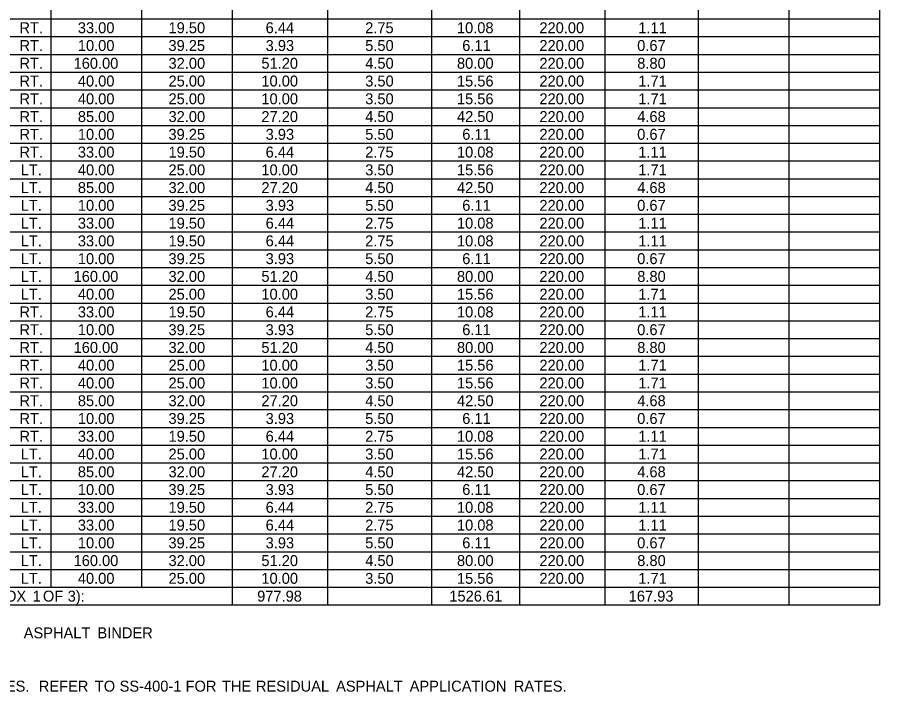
# Model space of a CAD drawing. Extents: x 544478 to 1930787, y -1948294 to 596640.
# Drawn here: x 550607 to 551080, y -1946928.5 to -1946558.2 of the extents above; entities that cross this region are included whole.
import ezdxf

# ---------------------------------------------------------------- set-up
doc = ezdxf.new("R2010")
doc.units = 0
doc.layers.add('Default', color=7, linetype='Continuous')

msp = doc.modelspace()

# ---------------------------------------------------------------- linework, layer by layer
at = {"layer": 'Default'}
for p, q in [((550625.62, -1946871.09), (550625.62, -1946192.49)), ((550675.35, -1946871.09), (550675.35, -1946192.49)), ((550777.23, -1946880.84), (550777.23, -1946192.49)), ((551079.97, -1946880.84), (551079.97, -1946192.49)), ((550725.07, -1946880.84), (550725.07, -1946217.84)), ((550834.27, -1946880.84), (550834.27, -1946217.84)), ((550882.53, -1946880.84), (550882.53, -1946217.84)), ((550929.33, -1946880.84), (550929.33, -1946217.84)), ((550980.52, -1946880.84), (550980.52, -1946217.84)), ((551030.25, -1946880.84), (551030.25, -1946217.84)), ((550675.35, -1946871.09), (550675.35, -1946237.34)), ((550834.27, -1946880.84), (550834.27, -1946237.34)), ((550625.62, -1946871.09), (550625.62, -1946247.09)), ((550725.07, -1946880.84), (550725.07, -1946247.09)), ((550882.53, -1946880.84), (550882.53, -1946247.09)), ((550257.56, -1946559.09), (551079.97, -1946559.09)), ((550929.33, -1946559.09), (551030.25, -1946559.09)), ((550503.26, -1946568.84), (551079.97, -1946568.84)), ((550503.26, -1946578.59), (551079.97, -1946578.59)), ((550503.26, -1946588.34), (551079.97, -1946588.34)), ((550503.26, -1946598.09), (551079.97, -1946598.09)), ((550503.26, -1946607.84), (551079.97, -1946607.84)), ((550503.26, -1946617.59), (551079.97, -1946617.59)), ((550503.26, -1946627.34), (551079.97, -1946627.34)), ((550503.26, -1946637.09), (551079.97, -1946637.09)), ((550503.26, -1946646.84), (551079.97, -1946646.84)), ((550503.26, -1946656.59), (551079.97, -1946656.59)), ((550503.26, -1946666.34), (551079.97, -1946666.34)), ((550503.26, -1946676.09), (550777.23, -1946676.09)), ((550725.07, -1946676.09), (550777.23, -1946676.09)), ((550777.23, -1946676.09), (551079.97, -1946676.09)), ((550503.26, -1946685.84), (551079.97, -1946685.84)), ((550503.26, -1946695.59), (550777.23, -1946695.59)), ((550725.07, -1946695.59), (550777.23, -1946695.59)), ((550777.23, -1946695.59), (551079.97, -1946695.59)), ((550503.26, -1946705.34), (550777.23, -1946705.34)), ((550725.07, -1946705.34), (550777.23, -1946705.34)), ((550777.23, -1946705.34), (551079.97, -1946705.34)), ((550257.56, -1946715.09), (551079.97, -1946715.09)), ((550503.26, -1946724.84), (551079.97, -1946724.84)), ((550503.26, -1946734.59), (551079.97, -1946734.59)), ((550503.26, -1946744.34), (551079.97, -1946744.34)), ((550503.26, -1946754.09), (551079.97, -1946754.09)), ((550503.26, -1946763.84), (551079.97, -1946763.84)), ((550503.26, -1946773.59), (551079.97, -1946773.59)), ((550503.26, -1946783.34), (551079.97, -1946783.34)), ((550503.26, -1946793.09), (551079.97, -1946793.09)), ((550503.26, -1946802.84), (551079.97, -1946802.84)), ((550503.26, -1946812.59), (551079.97, -1946812.59)), ((550503.26, -1946822.34), (551079.97, -1946822.34)), ((550503.26, -1946832.09), (550777.23, -1946832.09)), ((550725.07, -1946832.09), (550777.23, -1946832.09)), ((550777.23, -1946832.09), (551079.97, -1946832.09)), ((550503.26, -1946841.84), (551079.97, -1946841.84)), ((550503.26, -1946851.59), (550777.23, -1946851.59)), ((550725.07, -1946851.59), (550777.23, -1946851.59)), ((550777.23, -1946851.59), (551079.97, -1946851.59)), ((550503.26, -1946861.34), (550777.23, -1946861.34)), ((550725.07, -1946861.34), (550777.23, -1946861.34)), ((550777.23, -1946861.34), (551079.97, -1946861.34)), ((550257.56, -1946871.09), (551079.97, -1946871.09)), ((550929.33, -1946880.84), (550929.33, -1946871.09)), ((550503.26, -1946880.84), (551079.97, -1946880.84))]:
    msp.add_line(p, q, dxfattribs=at)

# ---------------------------------------------------------------- texts
for s, p in [(' RT.', (550605.95, -1946566.97)), ('33.00', (550640.2, -1946566.97)), ('19.50', (550689.93, -1946566.97)), ('6.44', (550743.2, -1946566.97)), ('2.75', (550797.77, -1946566.97)), ('10.08', (550848.1, -1946566.97)), ('220.00', (550893.32, -1946566.97)), ('1.11', (550947.55, -1946566.97)), (' RT.', (550605.95, -1946576.72)), ('10.00', (550640.2, -1946576.72)), ('39.25', (550689.89, -1946576.72)), ('3.93', (550743.19, -1946576.72)), ('5.50', (550797.8, -1946576.72)), ('6.11', (550851.02, -1946576.72)), ('220.00', (550893.32, -1946576.72)), ('0.67', (550946.96, -1946576.72)), (' RT.', (550605.95, -1946586.47)), ('160.00', (550637.87, -1946586.47)), ('32.00', (550689.93, -1946586.47)), ('51.20', (550740.87, -1946586.47)), ('4.50', (550797.8, -1946586.47)), ('80.00', (550848.12, -1946586.47)), ('220.00', (550893.32, -1946586.47)), ('8.80', (550946.98, -1946586.47)), (' RT.', (550605.95, -1946596.22)), ('40.00', (550640.2, -1946596.22)), ('25.00', (550689.93, -1946596.22)), ('10.00', (550740.87, -1946596.22)), ('3.50', (550797.8, -1946596.22)), ('15.56', (550848.11, -1946596.22)), ('220.00', (550893.32, -1946596.22)), ('1.71', (550947.55, -1946596.22)), (' RT.', (550605.95, -1946605.97)), ('40.00', (550640.2, -1946605.97)), ('25.00', (550689.93, -1946605.97)), ('10.00', (550740.87, -1946605.97)), ('3.50', (550797.8, -1946605.97)), ('15.56', (550848.11, -1946605.97)), ('220.00', (550893.32, -1946605.97)), ('1.71', (550947.55, -1946605.97)), (' RT.', (550605.95, -1946615.72)), ('85.00', (550640.2, -1946615.72)), ('32.00', (550689.93, -1946615.72)), ('27.20', (550740.87, -1946615.72)), ('4.50', (550797.8, -1946615.72)), ('42.50', (550848.12, -1946615.72)), ('220.00', (550893.32, -1946615.72)), ('4.68', (550946.96, -1946615.72)), (' RT.', (550605.95, -1946625.47)), ('10.00', (550640.2, -1946625.47)), ('39.25', (550689.89, -1946625.47)), ('3.93', (550743.19, -1946625.47)), ('5.50', (550797.8, -1946625.47)), ('6.11', (550851.02, -1946625.47)), ('220.00', (550893.32, -1946625.47)), ('0.67', (550946.96, -1946625.47)), (' RT.', (550605.95, -1946635.22)), ('33.00', (550640.2, -1946635.22)), ('19.50', (550689.93, -1946635.22)), ('6.44', (550743.2, -1946635.22)), ('2.75', (550797.77, -1946635.22)), ('10.08', (550848.1, -1946635.22)), ('220.00', (550893.32, -1946635.22)), ('1.11', (550947.55, -1946635.22)), (' LT.', (550606.65, -1946644.97)), ('40.00', (550640.2, -1946644.97)), ('25.00', (550689.93, -1946644.97)), ('10.00', (550740.87, -1946644.97)), ('3.50', (550797.8, -1946644.97)), ('15.56', (550848.11, -1946644.97)), ('220.00', (550893.32, -1946644.97)), ('1.71', (550947.55, -1946644.97)), (' LT.', (550606.65, -1946654.72)), ('85.00', (550640.2, -1946654.72)), ('32.00', (550689.93, -1946654.72)), ('27.20', (550740.87, -1946654.72)), ('4.50', (550797.8, -1946654.72)), ('42.50', (550848.12, -1946654.72)), ('220.00', (550893.32, -1946654.72)), ('4.68', (550946.96, -1946654.72)), (' LT.', (550606.65, -1946664.47)), ('10.00', (550640.2, -1946664.47)), ('39.25', (550689.89, -1946664.47)), ('3.93', (550743.19, -1946664.47)), ('5.50', (550797.8, -1946664.47)), ('6.11', (550851.02, -1946664.47)), ('220.00', (550893.32, -1946664.47)), ('0.67', (550946.96, -1946664.47)), (' LT.', (550606.65, -1946674.22)), ('33.00', (550640.2, -1946674.22)), ('19.50', (550689.93, -1946674.22)), ('6.44', (550743.2, -1946674.22)), ('2.75', (550797.77, -1946674.22)), ('10.08', (550848.1, -1946674.22)), ('220.00', (550893.32, -1946674.22)), ('1.11', (550947.55, -1946674.22)), (' LT.', (550606.65, -1946683.97)), ('33.00', (550640.2, -1946683.97)), ('19.50', (550689.93, -1946683.97)), ('6.44', (550743.2, -1946683.97)), ('2.75', (550797.77, -1946683.97)), ('10.08', (550848.1, -1946683.97)), ('220.00', (550893.32, -1946683.97)), ('1.11', (550947.55, -1946683.97)), (' LT.', (550606.65, -1946693.72)), ('10.00', (550640.2, -1946693.72)), ('39.25', (550689.89, -1946693.72)), ('3.93', (550743.19, -1946693.72)), ('5.50', (550797.8, -1946693.72)), ('6.11', (550851.02, -1946693.72)), ('220.00', (550893.32, -1946693.72)), ('0.67', (550946.96, -1946693.72)), (' LT.', (550606.65, -1946703.47)), ('160.00', (550637.87, -1946703.47)), ('32.00', (550689.93, -1946703.47)), ('51.20', (550740.87, -1946703.47)), ('4.50', (550797.8, -1946703.47)), ('80.00', (550848.12, -1946703.47)), ('220.00', (550893.32, -1946703.47)), ('8.80', (550946.98, -1946703.47)), (' LT.', (550606.65, -1946713.22)), ('40.00', (550640.2, -1946713.22)), ('25.00', (550689.93, -1946713.22)), ('10.00', (550740.87, -1946713.22)), ('3.50', (550797.8, -1946713.22)), ('15.56', (550848.11, -1946713.22)), ('220.00', (550893.32, -1946713.22)), ('1.71', (550947.55, -1946713.22)), (' RT.', (550605.95, -1946722.97)), ('33.00', (550640.2, -1946722.97)), ('19.50', (550689.93, -1946722.97)), ('6.44', (550743.2, -1946722.97)), ('2.75', (550797.77, -1946722.97)), ('10.08', (550848.1, -1946722.97)), ('220.00', (550893.32, -1946722.97)), ('1.11', (550947.55, -1946722.97)), (' RT.', (550605.95, -1946732.72)), ('10.00', (550640.2, -1946732.72)), ('39.25', (550689.89, -1946732.72)), ('3.93', (550743.19, -1946732.72)), ('5.50', (550797.8, -1946732.72)), ('6.11', (550851.02, -1946732.72)), ('220.00', (550893.32, -1946732.72)), ('0.67', (550946.96, -1946732.72)), (' RT.', (550605.95, -1946742.47)), ('160.00', (550637.87, -1946742.47)), ('32.00', (550689.93, -1946742.47)), ('51.20', (550740.87, -1946742.47)), ('4.50', (550797.8, -1946742.47)), ('80.00', (550848.12, -1946742.47)), ('220.00', (550893.32, -1946742.47)), ('8.80', (550946.98, -1946742.47)), (' RT.', (550605.95, -1946752.22)), ('40.00', (550640.2, -1946752.22)), ('25.00', (550689.93, -1946752.22)), ('10.00', (550740.87, -1946752.22)), ('3.50', (550797.8, -1946752.22)), ('15.56', (550848.11, -1946752.22)), ('220.00', (550893.32, -1946752.22)), ('1.71', (550947.55, -1946752.22)), (' RT.', (550605.95, -1946761.97)), ('40.00', (550640.2, -1946761.97)), ('25.00', (550689.93, -1946761.97)), ('10.00', (550740.87, -1946761.97)), ('3.50', (550797.8, -1946761.97)), ('15.56', (550848.11, -1946761.97)), ('220.00', (550893.32, -1946761.97)), ('1.71', (550947.55, -1946761.97)), (' RT.', (550605.95, -1946771.72)), ('85.00', (550640.2, -1946771.72)), ('32.00', (550689.93, -1946771.72)), ('27.20', (550740.87, -1946771.72)), ('4.50', (550797.8, -1946771.72)), ('42.50', (550848.12, -1946771.72)), ('220.00', (550893.32, -1946771.72)), ('4.68', (550946.96, -1946771.72)), (' RT.', (550605.95, -1946781.47)), ('10.00', (550640.2, -1946781.47)), ('39.25', (550689.89, -1946781.47)), ('3.93', (550743.19, -1946781.47)), ('5.50', (550797.8, -1946781.47)), ('6.11', (550851.02, -1946781.47)), ('220.00', (550893.32, -1946781.47)), ('0.67', (550946.96, -1946781.47)), (' RT.', (550605.95, -1946791.22)), ('33.00', (550640.2, -1946791.22)), ('19.50', (550689.93, -1946791.22)), ('6.44', (550743.2, -1946791.22)), ('2.75', (550797.77, -1946791.22)), ('10.08', (550848.1, -1946791.22)), ('220.00', (550893.32, -1946791.22)), ('1.11', (550947.55, -1946791.22)), (' LT.', (550606.65, -1946800.97)), ('40.00', (550640.2, -1946800.97)), ('25.00', (550689.93, -1946800.97)), ('10.00', (550740.87, -1946800.97)), ('3.50', (550797.8, -1946800.97)), ('15.56', (550848.11, -1946800.97)), ('220.00', (550893.32, -1946800.97)), ('1.71', (550947.55, -1946800.97)), (' LT.', (550606.65, -1946810.72)), ('85.00', (550640.2, -1946810.72)), ('32.00', (550689.93, -1946810.72)), ('27.20', (550740.87, -1946810.72)), ('4.50', (550797.8, -1946810.72)), ('42.50', (550848.12, -1946810.72)), ('220.00', (550893.32, -1946810.72)), ('4.68', (550946.96, -1946810.72)), (' LT.', (550606.65, -1946820.47)), ('10.00', (550640.2, -1946820.47)), ('39.25', (550689.89, -1946820.47)), ('3.93', (550743.19, -1946820.47)), ('5.50', (550797.8, -1946820.47)), ('6.11', (550851.02, -1946820.47)), ('220.00', (550893.32, -1946820.47)), ('0.67', (550946.96, -1946820.47)), (' LT.', (550606.65, -1946830.22)), ('33.00', (550640.2, -1946830.22)), ('19.50', (550689.93, -1946830.22)), ('6.44', (550743.2, -1946830.22)), ('2.75', (550797.77, -1946830.22)), ('10.08', (550848.1, -1946830.22)), ('220.00', (550893.32, -1946830.22)), ('1.11', (550947.55, -1946830.22)), (' LT.', (550606.65, -1946839.97)), ('33.00', (550640.2, -1946839.97)), ('19.50', (550689.93, -1946839.97)), ('6.44', (550743.2, -1946839.97)), ('2.75', (550797.77, -1946839.97)), ('10.08', (550848.1, -1946839.97)), ('220.00', (550893.32, -1946839.97)), ('1.11', (550947.55, -1946839.97)), (' LT.', (550606.65, -1946849.72)), ('10.00', (550640.2, -1946849.72)), ('39.25', (550689.89, -1946849.72)), ('3.93', (550743.19, -1946849.72)), ('5.50', (550797.8, -1946849.72)), ('6.11', (550851.02, -1946849.72)), ('220.00', (550893.32, -1946849.72)), ('0.67', (550946.96, -1946849.72)), (' LT.', (550606.65, -1946859.47)), ('160.00', (550637.87, -1946859.47)), ('32.00', (550689.93, -1946859.47)), ('51.20', (550740.87, -1946859.47)), ('4.50', (550797.8, -1946859.47)), ('80.00', (550848.12, -1946859.47)), ('220.00', (550893.32, -1946859.47)), ('8.80', (550946.98, -1946859.47)), (' LT.', (550606.65, -1946869.22)), ('40.00', (550640.2, -1946869.22)), ('25.00', (550689.93, -1946869.22)), ('10.00', (550740.87, -1946869.22)), ('3.50', (550797.8, -1946869.22)), ('15.56', (550848.11, -1946869.22)), ('220.00', (550893.32, -1946869.22)), ('1.71', (550947.55, -1946869.22)), (' BOX', (550592.71, -1946878.97)), (' 1', (550613.2, -1946878.97)), (' OF', (550618.83, -1946878.97)), (' 3):', (550632.41, -1946878.97)), ('977.98', (550738.53, -1946878.97)), ('1526.61', (550843.94, -1946878.97)), ('167.93', (550942.3, -1946878.97)), ('  ASPHALT', (550606.05, -1946899.14)), (' BINDER', (550648.75, -1946899.14)), (' RATES.', (550582.44, -1946928.39)), ('  REFER', (550614.32, -1946928.39)), (' TO', (550647.28, -1946928.39)), (' SS-400-1', (550660.87, -1946928.39)), (' FOR', (550697.07, -1946928.39)), (' THE', (550716.98, -1946928.39)), (' RESIDUAL', (550735.63, -1946928.39)), (' ASPHALT', (550779.59, -1946928.39)), (' APPLICATION', (550819.96, -1946928.39)), (' RATES.', (550877.04, -1946928.39))]:
    msp.add_text(s, height=6, dxfattribs=at).set_placement(p)

doc.saveas('drawing.dxf')
